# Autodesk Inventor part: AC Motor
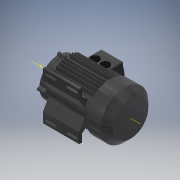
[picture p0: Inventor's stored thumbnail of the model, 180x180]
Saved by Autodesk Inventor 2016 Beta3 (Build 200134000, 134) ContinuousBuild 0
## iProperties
Part Number: AC Motor
Document SubType Name: Modeling
Created: 2003-05
Description: ac-motor.ipt.
Density: 1 g/cm^3
Mass: 2583.35 g
Surface Area: 6107.9 cm^2
Volume: 2583.35 cm^3
Material: Generic
Appearance: Skid Plate
+MSCProtocol1+ProtocolID: P00030526084445659
+MSCProtocol2+Protocol: P00030526084445659<@PID>[Version]<@EL>Version=2.2<@EL>[Baseview]<@EL>InOpt=0<@EL>H2=574<@EL>W2=514<@EL>Top=160<@EL>Left=357<@EL>OnTop=0<@EL>UpdateAll=0<@EL>Enab
Control State: 0
Master: False
Checked Out: False
Shininess: 64.0
Length Units: 11272
Angle Units: 11279
Time Units: 11290
Mass Units: 11286
Length Display Precision: 3
Angle Display Precision: 2
Compacted: True
Density: 0.0
Volumn: 0.0
Area: 0.0
PropertySet Name: Model Information
Author: Autodesk, Inc.
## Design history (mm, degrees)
sketch "Sketch1"
  geometry: L1 (0, 0)-(0, 45); L2 (6, 78)-(220, 78); L3 (220, 78)-(220, 98); L4 (220, 98)-(279.5, 98); L5 (279.5, 98)-(305, 72.5); L6 (305, 72.5)-(305, 0); L7 (305, 0)-(0, 0); L8 (0, 45)-(5, 45); L9 (5, 45)-(5, 60); L10 (5, 60)-(6, 60); L11 (6, 60)-(6, 78); L12 (220, 19)-(-5, 19); L13 (-5, 19)-(-5, 14); L14 (-5, 14)-(-65, 14); L15 (-65, 14)-(-65, 0); L16 (220, 19)-(220, 14); L17 (220, 14)-(279.5, 14); L18 (279.5, 14)-(279.5, 0); L19 (-65, 0)-(305, 0); L20 (305, 0)-(0, 0); L21 (0, 20)-(15, 20); L22 (15, 20)-(15, 68); L23 (15, 68)-(223, 68); L24 (223, 68)-(223, 95); L25 (223, 95)-(278.257, 95); L26 (278.257, 95)-(302, 71.257); L27 (302, 71.257)-(302, 0); L28 (-65, 0)-(279.5, 0); 3 further points
  constraints: 56 end point, 13 parallel, 10 perpendicular, 10 point on line, 3 collinear, 1 vertical, 1 other
  dimensions: "d0" = 196 diameter of L4 L7; "d4" = 63 distance from line of point (63, 0) L1; "d5" = 28 diameter of L14 L7; "d6" = 45 deg angle of L4 L5; "d8" = 60 distance of L13.end L14.end; "d9" = 1 distance between parallel lines of L11 L9; "d10" = 5 distance between parallel lines of L1 L9; "d12" = 5 distance between parallel lines of L13 L1; "d13" = 5 distance between parallel lines of L12 L14; "d17" = 25.5 horizontal distance of L4.end L5.end (derived); "d18" = 3 distance between parallel lines of L6 L27; "d19" = 3 distance between parallel lines of L5 L26; "d20" = 3 distance between parallel lines of L25 L4; "d21" = 3 distance between parallel lines of L3 L24; "d22" = 10 distance between parallel lines of L2 L23; "d23" = 15 distance between parallel lines of L1 L22; "d25" = 1 distance between parallel lines of L12 L21; "d79" = 78 distance between parallel lines of L2 L28 (= d67); "d180" = 25 distance between parallel lines of L8 L21; "d181" = 40 distance between parallel lines of L21 L10; "Size" = 310 distance between parallel lines of L13 L6; "d183" = 85 distance between parallel lines of L6 L3; "d184" = 44 distance from line of L1 point (44, 0); "d185" = 27 distance from line of point (193, 0) L3
revolve "Revolution1" stored, may be unused: angle "d24" = 90 deg
workplane "Work Plane8"
sketch "Sketch3"
  geometry: L1 (-100, 56)-(-100, 98); L2 (-100, 98)-(-88, 98); L3 (-88, 98)-(-88, 66); L4 (-88, 66)-(-63.435, 45.387); L5 (-100, 56)-(-76.489, 15.278); L6 (-76.489, -15.278)-(-100, -56); L7 (-100, -56)-(-100, -98); L8 (-100, -98)-(-88, -98); L9 (-88, -98)-(-88, -66); L10 (-88, -66)-(-63.435, -45.387); A1 r 78 centre (0, 0) between (-63.435, -45.387) and (-63.435, 45.387) reference; 3 further points
  constraints: 20 end point, 4 point on circle, 4 vertical alignment, 3 equal length, 3 parallel, 2 perpendicular, 2 point on line, 1 vertical
  dimensions: "d28" = 42 distance of L1.start L1.end; "d29" = 12 distance of L1.end L2.end; "d30" = 196 distance between parallel lines of L8 L2; "d31" = 20 deg angle of L10 L6; "d33" = 30 deg angle of L6 L7; "d38" = 160 distance of point (-100, -80) point (-100, 80); "d39" = 18 distance from line of L8 point (-100, -80) (= -0.5 x d38 + 0.5 x d30); "d53" = 10 vertical distance of L1.start L3.end (computed from d29); "d54" = 100 distance from line of point (0, 0) L7
extrude "Extrusion1" join sketch "Sketch3" stored distance "d35" = 176 (= d2); taper "d36" = 0 deg
workplane "Work Plane1"
sketch "Sketch2"
  geometry: L1 (49.84, 60)-(128, 60); L2 (128, 60)-(128, 45); L3 (49.84, -60)-(128, -60); L4 (128, -60)-(128, -45); L5 (-120.6, 0)-(177.6, 0) reference; A1 r 148.143 centre (-13.143, 0) between (128, -45) and (128, 45); A2 r 78 centre (0, 0) between (49.84, 60) and (49.84, -60) reference
  constraints: 8 end point, 4 point on circle, 3 perpendicular, 2 point on line, 1 centre point, 1 horizontal, 1 vertical alignment
  dimensions: "d57" = 7 distance edge to line of A1 L2; "d58" = 15 distance of L1.end L2.end; "d60" = 120 distance between parallel lines of L3 L1; "d186" = 128 distance from line of A2.centre L4
extrude "Extrusion2" join sketch "Sketch2" stored distance "d62" = 92 (computed from d27); taper "d63" = 0 deg
sketch "Sketch5"
  geometry: L1 (0, 0)-(92, 0) reference; L2 (0, 0)-(0, -78.16) reference; L3 (-117, -128)-(310, -128) reference; L4 (46, 54)-(46, -275) reference; L5 (67, -50)-(25, -50); C1 r 16.25 at (25, -50); C2 r 16.25 at (67, -50); 2 further points
  constraints: 2 centre point, 2 end point, 2 point on line, 1 equal radius, 1 horizontal alignment, 1 midpoint, 1 parallel, 1 perpendicular
  dimensions: "d61" = 32.5 diameter of C1; "d66" = 42 distance of L5.start L5.end; "d67" = 78 distance from line of L3 L5.end; "d68" = 25 distance from line of L1 point (0, -25)
extrude "Extrusion3" join sketch "Sketch5" distance "d69" = 3; taper "d70" = 0 deg
workplane "Work Plane3"
sketch "Sketch7"
  geometry: L1 (92, 0)-(92, 120) reference; L2 (0, 120)-(0, 0) reference; L3 (0, 120)-(92, 120) reference; L4 (0, 0)-(92, 0) reference; L5 (1, 1)-(1, 119); L6 (1, 119)-(91, 119); L7 (91, 119)-(91, 1); L8 (91, 1)-(1, 1)
  constraints: 8 end point, 3 other
  dimensions: "d75" = 1 distance between parallel lines of L1 L7
extrude "Extrusion4" cut sketch "Sketch7" stored distance "d76" = 1; taper "d77" = 0 deg
workplane "Work Plane4"
sketch "Sketch8"
  geometry: C1 r 78 at (0, 0) reference; C2 r 77 at (0, 0)
  constraints: 1 centre point
  dimensions: "d81" = 1 radial gap between concentric circles of C1 C2
extrude "Extrusion5" cut sketch "Sketch8" stored distance "d82" = 1; taper "d83" = 0 deg
sketch "Sketch10"
  geometry: L1 (-5.796, 85.553)-(-7.928, 77.596); L2 (5.796, 85.553)-(7.928, 77.596); C1 r 77 at (0, 0) reference; A1 r 78 centre (0, 0) between (-7.928, 77.596) and (7.928, 77.596) reference; A2 r 6 centre (0, 84) between (5.796, 85.553) and (-5.796, 85.553); 1 further point
  constraints: 7 point on circle, 4 end point, 2 point on line, 2 tangent, 2 vertical alignment, 1 centre point, 1 horizontal alignment
  dimensions: "d89" = 6 radius of A2; "d90" = 6 distance of point (0, 78) A2.centre; "d91" = 30 deg angle of L2 L1
extrude "Extrusion7" join sketch "Sketch10" distance "d92" = 15; taper "d93" = 0 deg
sketch "Sketch11"
  geometry: L1 (5.796, 85.553)-(7.928, 77.596) reference; L2 (-7.928, 77.596)-(-5.796, 85.553) reference; A1 r 78 centre (0, 0) between (7.928, 77.596) and (-7.928, 77.596) reference; A2 r 6 centre (0, 84) between (5.796, 85.553) and (-5.796, 85.553) reference
extrude "Extrusion8" join sketch "Sketch11" distance "d94" = 13 (computed from d80); taper "d95" = 0 deg
sketch "Sketch12"
  geometry: A1 r 6 centre (0, 84) between (5.796, 85.553) and (-5.796, 85.553) reference
hole "Hole2" sketch "Sketch12" at (0, 84) diameter "d96" = 6; stored, may be unused: countersink angle "d100" = 82 deg, drill point angle "d102" = 118 deg; dims "d97" = 6, "d98" = 4, "d99" = 2, "d101" = 8
pattern_circular "Circular Pattern1" dims "d105" = 360 deg
fillet "Fillet1" dims "d106" = 2, "d188" = -10 (derived)
workplane "Work Plane5"
workplane "Work Plane6"
sketch "Sketch13"
  geometry: L1 (77.356, 10)-(95.071, 10); L2 (95.071, 10)-(95.071, 12); L3 (95.071, 12)-(77.071, 12); L4 (75.078, 21.15)-(92.793, 21.15); L5 (92.793, 21.15)-(92.793, 23.15); L6 (92.793, 23.15)-(74.485, 23.15); L7 (70.998, 32.3)-(88.713, 32.3); L8 (88.713, 32.3)-(88.713, 34.3); L9 (88.713, 34.3)-(70.054, 34.3); L10 (64.777, 43.45)-(82.492, 43.45); L11 (82.492, 43.45)-(82.492, 45.45); L12 (82.492, 45.45)-(63.39, 45.45); L13 (77.356, -10)-(95.071, -10); L14 (95.071, -10)-(95.071, -12); L15 (95.071, -12)-(77.071, -12); L16 (75.078, -21.15)-(92.485, -21.15); L17 (92.485, -21.15)-(92.485, -23.15); L18 (92.485, -23.15)-(74.485, -23.15); L19 (70.998, -32.3)-(88.054, -32.3); L20 (88.054, -32.3)-(88.054, -34.3); L21 (88.054, -34.3)-(70.054, -34.3); L22 (64.777, -43.45)-(81.39, -43.45); L23 (81.39, -43.45)-(81.39, -45.45); L24 (81.39, -45.45)-(63.39, -45.45); L25 (55.703, -54.6)-(71.67, -54.6); L26 (71.67, -54.6)-(71.67, -56.6); L27 (71.67, -56.6)-(53.67, -56.6); 1 further point
  constraints: 54 end point, 16 parallel, 11 equal length, 10 perpendicular, 1 horizontal, 1 vertical alignment, 19 other
  dimensions: "d110" = 2 distance of L1.end L2.end; "d112" = 10 distance from line of L1 point (0, 0); "d118" = 10 distance from line of L13 point (0, 0); "d122" = 18 distance of L17.end L18.end (= d123); "d123" = 18 distance of L14.end L15.end (computed from d67, d0); "d124" = 18 distance of L20.end L21.end (= d123); "d125" = 18 distance of L23.end L24.end (= d123); "d131" = 18 distance of L26.end L27.end (= d123); "d149" = 11.15 distance between parallel lines of L4 L1 (computed from d67); "d150" = 11.15 distance between parallel lines of L7 L4 (= d149); "d151" = 11.15 distance between parallel lines of L10 L7 (= d149); "d152" = 11.15 distance between parallel lines of L16 L13 (= d149); "d153" = 11.15 distance between parallel lines of L19 L16 (= d149); "d154" = 11.15 distance between parallel lines of L22 L19 (= d149); "d155" = 11.15 distance between parallel lines of L25 L22 (= d149)
extrude "Extrusion9" join sketch "Sketch13" stored distance "d108" = 10; taper "d109" = 0 deg
workplane "Work Plane7"
sketch "Sketch14"
  geometry: L1 (7, 77.685)-(7, 95.685); L2 (7, 95.685)-(9, 95.685); L3 (9, 95.685)-(9, 77.479); L4 (18.15, 75.859)-(18.15, 93.559); L5 (18.15, 93.559)-(20.15, 93.559); L6 (20.15, 93.559)-(20.15, 75.352); L7 (29.3, 72.288)-(29.3, 89.651); L8 (29.3, 89.651)-(31.3, 89.651); L9 (31.3, 89.651)-(31.3, 71.444); L10 (40.45, 66.692)-(40.45, 84.692); L11 (40.45, 84.692)-(42.45, 84.692); L12 (42.45, 84.692)-(42.45, 65.437); L13 (51.6, 58.493)-(51.6, 74.872); L14 (51.6, 74.872)-(53.6, 74.872); L15 (53.6, 74.872)-(53.6, 56.666); 1 further point
  constraints: 30 end point, 15 parallel, 6 perpendicular, 1 vertical, 11 other
  dimensions: "d132" = 7 distance from line of point (0, 0) L1; "d134" = 2 distance between parallel lines of L3 L1; "d138" = 18 distance of L1.start L1.end (= d123); "d156" = 11.15 distance between parallel lines of L4 L1 (= d149); "d157" = 11.15 distance between parallel lines of L7 L4 (= d149); "d158" = 11.15 distance between parallel lines of L10 L7 (= d149); "d159" = 11.15 distance between parallel lines of L13 L10 (= d149); "d178" = 18 distance of L10.start L10.end (= d123)
extrude "Extrusion10" join sketch "Sketch14" stored distance "d140" = 10; taper "d141" = 0 deg
sketch "Sketch15"
  geometry: L1 (53.6, 56.666)-(63.39, 45.45); L2 (58.101, 52.041)-(71.662, 63.878); L3 (71.662, 63.878)-(72.977, 62.371); L4 (72.977, 62.371)-(59.416, 50.535); L5 (58.495, 51.058)-(72.319, 63.125); A1 r 78 centre (0, 0) between (53.6, 56.666) and (63.39, 45.45) reference
  constraints: 10 end point, 2 midpoint, 2 parallel, 2 point on circle, 1 perpendicular, 1 point on line
  dimensions: "d146" = 2 distance of L2.end L3.end; "d160" = 18 distance of L3.end L4.end (= d123)
extrude "Extrusion11" join sketch "Sketch15" stored distance "d147" = 10; taper "d148" = 0 deg
mirror "Mirror4"
fillet "Fillet2" dims "d142" = 5, "d189" = -10 (derived)
fillet "Fillet3" dims "d143" = 4, "d190" = -10 (derived)
fillet "Fillet4" dims "d144" = 2, "d145" = 4, "d191" = -10 (derived)
workpoint "Work Point1"
sketch "Sketch19"
  geometry: L1 (0, 0)-(149, 0) reference; L2 (10.254, 11.113)-(48.354, 11.113); L3 (48.354, 11.113)-(48.354, 20.638); L4 (48.354, 20.638)-(10.254, 20.637); L5 (10.254, 20.637)-(10.254, 11.113); 2 further points
  constraints: 8 end point, 2 midpoint, 2 parallel, 2 vertical alignment, 1 horizontal, 1 perpendicular, 4 other
  dimensions: "d194" = 15.875 distance from line of L1 point (10.254, 15.875); "d195" = 9.525 distance between parallel lines of L4 L2; "d196" = 38.1 distance between parallel lines of L3 L5
extrude "Extrusion13" cut sketch "Sketch19" stored distance "d197" = 10; taper "d198" = 0 deg
pattern_linear "Rectangular Pattern2" dims "d201" = 88.9, "d204" = 165.1
workaxis "Work Axis2"
body "Solid1"
workplane "Work Plane"
other parameters: "d2" = 176, "d3" = 23 (= -0.5 x d1 + 0.5 x d37), "d7" = 372, "d27" = 102, "d37" = 186 (computed from d2), "d80" = -16, "d107" = 5, "d117" = 5, "d139" = 5
